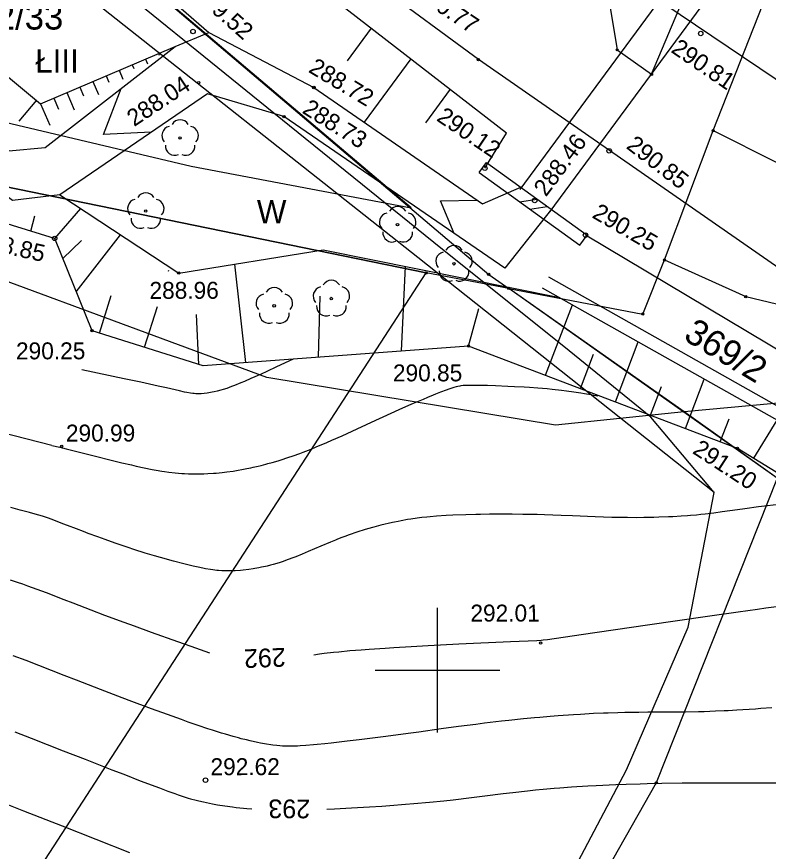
# Model space of a CAD drawing. Extents: x 7477803 to 7478145, y 5500698 to 5500984.
# Drawn here: x 7477883.12 to 7477913.26, y 5500892.73 to 5500926.22 of the extents above; entities that cross this region are included whole.
import ezdxf

# ---------------------------------------------------------------- set-up
doc = ezdxf.new("R2010")
doc.units = 0
for name, color, linetype in [('203-Punkt załamania granicy działki nie stabilizowany', 7, 'Continuous'), ('eNN', 7, 'Continuous'), ('eWN', 7, 'Continuous'), ('gr_dzialki', 7, 'Continuous'), ('gr_klasy', 7, 'Continuous'), ('gr_uzytek', 7, 'Continuous'), ('jezdnia', 7, 'Continuous'), ('murek', 7, 'Continuous'), ('nr_dzialki', 7, 'Continuous'), ('opis_klasy', 7, 'Continuous'), ('opis_uzytek', 7, 'Continuous'), ('pkt_wys', 7, 'Continuous'), ('przepust_rzut', 7, 'Continuous'), ('robocza49', 7, 'Continuous'), ('rowy', 7, 'Continuous'), ('skarp_wypel', 7, 'Continuous'), ('skarpa_gora', 7, 'Continuous'), ('warst_ciagla', 7, 'Continuous'), ('warst_opis', 7, 'Continuous'), ('warst_przeryw', 7, 'Continuous'), ('zielen', 7, 'Continuous')]:
    doc.layers.add(name, color=color, linetype=linetype)

# ---------------------------------------------------------------- blocks, each defined once
blk = doc.blocks.new('203')
blk.add_circle((0, 0), 0.045)
blk = doc.blocks.new('801_3')
at = {"layer": 'pkt_wys'}
blk.add_circle((0, 0), 0.045, dxfattribs=at)
blk.add_circle((0, 0), 0.045, dxfattribs=at)
blk = doc.blocks.new('922_5')
at = {"layer": 'zielen'}
blk.add_circle((-0.001, 0), 0.05, dxfattribs=at)
blk.add_circle((-0.001, 0), 0.05, dxfattribs=at)
for centre, start, end in [((0.004, 0.357), 30.1243, 149.8757), ((-0.353, 0.098), 101.9988, 221.9759), ((0.361, 0.098), 318.0241, 78.0012), ((-0.215, -0.321), 174.335, 293.7607), ((0.224, -0.321), 246.2393, 5.665)]:
    blk.add_arc(centre, 0.375, start, end, dxfattribs=at)
blk = doc.blocks.new('801_5')
at = {"layer": 'pkt_wys'}
blk.add_circle((0, 0), 0.05, dxfattribs=at)
blk.add_circle((0, 0), 0.05, dxfattribs=at)

msp = doc.modelspace()

# ---------------------------------------------------------------- linework, layer by layer
at = {"layer": 'eNN'}
msp.add_line((7477911.094, 5500907.132), (7477908.551, 5500910.148), dxfattribs=at)
msp.add_lwpolyline([(7477908.551, 5500910.148), (7477905.276, 5500912.813), (7477899.85, 5500917.156), (7477893.431, 5500922.355), (7477885.497, 5500928.781), (7477881.972, 5500929.954)], dxfattribs=at)
at = {"layer": 'eWN'}
msp.add_lwpolyline([(7477864.586, 5500830.869), (7477874.504, 5500845.51), (7477886.717, 5500863.094), (7477896.968, 5500876.013), (7477903.181, 5500887.651), (7477907.573, 5500896.009), (7477910.052, 5500901.721), (7477911.094, 5500907.132), (7477899.209, 5500916.554), (7477885.259, 5500927.591), (7477881.972, 5500929.954), (7477875.911, 5500934.547), (7477875.795, 5500934.654)], dxfattribs=at)
at = {"layer": 'gr_dzialki'}
for points in [[(7477905.2, 5500937.01), (7477907.2, 5500924.89)], [(7477877.66, 5500936.58), (7477902.05, 5500915.88)], [(7477908.58, 5500923.91), (7477911.91, 5500931.81)], [(7477911.05, 5500921.65), (7477914.31, 5500929.95)], [(7477907.2, 5500924.89), (7477908.58, 5500923.91)], [(7477909.1, 5500916.46), (7477911.05, 5500921.65)], [(7477911.05, 5500921.65), (7477913.61, 5500920.37)], [(7477880.41, 5500919.86), (7477899.54, 5500915.94)], [(7477908.23, 5500914.29), (7477909.1, 5500916.46)], [(7477909.1, 5500916.46), (7477912.36, 5500914.99)], [(7477867.65, 5500866.83), (7477899.54, 5500915.94)], [(7477902.85, 5500915.32), (7477899.54, 5500915.94)], [(7477902.05, 5500915.88), (7477902.85, 5500915.32)], [(7477913.62, 5500907.71), (7477902.85, 5500915.32)], [(7477902.85, 5500915.32), (7477908.23, 5500914.29)], [(7477912.36, 5500914.99), (7477916.11, 5500914.1)], [(7477913.62, 5500907.71), (7477908.77, 5500895.48)], [(7477908.77, 5500895.48), (7477894.92, 5500871.04)]]:
    msp.add_lwpolyline(points, dxfattribs=at)
at = {"layer": 'gr_klasy'}
for points in [[(7477898.94, 5500918.55), (7477879.178, 5500935.294)], [(7477881.9, 5500922.16), (7477890.12, 5500920.23)], [(7477890.12, 5500920.23), (7477898.94, 5500918.55)], [(7477893.15, 5500911.75), (7477871.161, 5500919.882)], [(7477899.54, 5500915.94), (7477880.41, 5500919.86)], [(7477902.85, 5500915.32), (7477899.54, 5500915.94)], [(7477909.89, 5500910.36), (7477902.85, 5500915.32)], [(7477904.73, 5500909.83), (7477893.15, 5500911.75)], [(7477909.89, 5500910.36), (7477904.73, 5500909.83)], [(7477913.62, 5500907.71), (7477909.89, 5500910.36)]]:
    msp.add_lwpolyline(points, dxfattribs=at)
at = {"layer": 'gr_uzytek'}
msp.add_lwpolyline([(7477929.78, 5500918.89), (7477938.86, 5500913.04), (7477909.89, 5500910.36)], dxfattribs=at)
at = {"layer": 'jezdnia'}
for points in [[(7477897.344, 5500935.024), (7477905.871, 5500928.923), (7477941.067, 5500905.192)], [(7477987.535, 5500870.412), (7477985.624, 5500871.53), (7477967.072, 5500882.45), (7477949.37, 5500893.011), (7477933.46, 5500902.673), (7477915.126, 5500915.133), (7477901.636, 5500924.498), (7477893.479, 5500930.51)]]:
    msp.add_lwpolyline(points, dxfattribs=at)
at = {"layer": 'murek'}
for p, q in [((7477901.667, 5500919.964), (7477901.96, 5500920.369)), ((7477901.96, 5500920.369), (7477905.993, 5500917.453)), ((7477901.667, 5500919.964), (7477905.7, 5500917.048)), ((7477903.288, 5500918.792), (7477903.986, 5500918.904)), ((7477903.693, 5500918.499), (7477904.391, 5500918.611)), ((7477905.7, 5500917.048), (7477905.993, 5500917.453))]:
    msp.add_line(p, q, dxfattribs=at)
at = {"layer": 'pkt_wys'}
for centre in [(7477890.19, 5500925.63), (7477910.553, 5500925.545), (7477906.881, 5500920.839), (7477901.895, 5500920.14), (7477903.895, 5500918.844), (7477905.932, 5500917.459), (7477884.641, 5500917.325), (7477890.69, 5500895.587)]:
    msp.add_circle(centre, 0.09, dxfattribs=at)
at = {"layer": 'przepust_rzut'}
for points in [[(7477910.779, 5500929.455), (7477903.291, 5500919.29)], [(7477911.987, 5500928.565), (7477904.499, 5500918.4)]]:
    msp.add_lwpolyline(points, dxfattribs=at)
at = {"layer": 'robocza49'}
for p, q in [((7477900, 5500897.5), (7477900, 5500902.5)), ((7477897.5, 5500900), (7477902.5, 5500900))]:
    msp.add_line(p, q, dxfattribs=at)
at = {"layer": 'rowy'}
for points in [[(7477872.777, 5500927.493), (7477873.773, 5500927.288), (7477878.954, 5500925.794), (7477882.8, 5500920.838), (7477884.259, 5500920.969), (7477889.475, 5500925.025), (7477890.824, 5500925.587), (7477895.037, 5500923.381), (7477901.802, 5500918.709), (7477903.365, 5500919.391)], [(7477904.573, 5500918.501), (7477902.695, 5500916.13), (7477893.838, 5500922.21), (7477890.767, 5500923.127), (7477884.852, 5500919.07), (7477882.952, 5500918.848), (7477877.738, 5500922.782), (7477873.234, 5500925.927), (7477872.495, 5500926.12)], [(7477888.516, 5500921.583), (7477886.602, 5500921.494), (7477887.31, 5500923.342)], [(7477900.658, 5500917.528), (7477900.117, 5500918.835), (7477901.575, 5500918.865)], [(7477993.882, 5500863.302), (7477915.697, 5500909.43), (7477904.458, 5500915.769)], [(7477993.629, 5500862.871), (7477915.447, 5500908.997), (7477904.213, 5500915.334)]]:
    msp.add_lwpolyline(points, dxfattribs=at)
at = {"layer": 'skarp_wypel'}
for p, q in [((7477897.341, 5500925.759), (7477896.374, 5500924.447)), ((7477889.329, 5500924.963), (7477889.339, 5500924.94)), ((7477888.804, 5500924.74), (7477888.83, 5500924.679)), ((7477887.753, 5500924.293), (7477887.82, 5500924.136)), ((7477888.279, 5500924.516), (7477888.36, 5500924.326)), ((7477898.922, 5500924.533), (7477897.048, 5500921.992)), ((7477887.228, 5500924.069), (7477887.381, 5500923.711)), ((7477886.178, 5500923.623), (7477886.402, 5500923.097)), ((7477886.703, 5500923.846), (7477886.81, 5500923.594)), ((7477885.653, 5500923.399), (7477885.801, 5500923.052)), ((7477900.503, 5500923.307), (7477899.51, 5500921.96)), ((7477883.906, 5500922.872), (7477883.2, 5500922.026)), ((7477884.603, 5500922.953), (7477884.791, 5500922.51)), ((7477885.128, 5500923.176), (7477885.423, 5500922.483)), ((7477884.078, 5500922.729), (7477884.443, 5500921.869)), ((7477884.641, 5500917.325), (7477885.686, 5500918.521)), ((7477883.691, 5500917.619), (7477883.841, 5500918.23)), ((7477884.969, 5500916.513), (7477885.721, 5500917.235)), ((7477885.505, 5500915.186), (7477887.28, 5500917.472)), ((7477892.308, 5500912.344), (7477891.862, 5500916.298)), ((7477898.556, 5500912.808), (7477898.711, 5500916.203)), ((7477889.208, 5500916.012), (7477889.219, 5500916.046)), ((7477886.437, 5500913.527), (7477886.912, 5500915.035)), ((7477895.223, 5500912.56), (7477895.289, 5500915.008)), ((7477888.246, 5500912.957), (7477888.759, 5500914.587)), ((7477901.238, 5500913.008), (7477901.656, 5500914.509)), ((7477904.329, 5500911.835), (7477905.406, 5500914.661)), ((7477890.422, 5500912.272), (7477890.325, 5500914.267)), ((7477907.133, 5500910.767), (7477908.048, 5500913.17)), ((7477905.731, 5500911.301), (7477906.258, 5500912.685)), ((7477909.936, 5500909.699), (7477910.691, 5500911.68)), ((7477908.534, 5500910.233), (7477908.974, 5500911.387)), ((7477911.338, 5500909.165), (7477911.69, 5500910.089)), ((7477912.677, 5500908.503), (7477913.613, 5500910.032))]:
    msp.add_line(p, q, dxfattribs=at)
at = {"layer": 'skarpa_gora'}
for points in [[(7477876.391, 5500937.758), (7477881.125, 5500933.996), (7477890.824, 5500925.587)], [(7477901.895, 5500920.141), (7477902.769, 5500921.55), (7477892.66, 5500929.389)], [(7477873.01, 5500928.626), (7477873.731, 5500928.508), (7477878.262, 5500927.583), (7477884.078, 5500922.729), (7477889.475, 5500925.025)], [(7477884.64, 5500917.325), (7477873.74, 5500920.698)], [(7477884.852, 5500919.07), (7477889.615, 5500915.935), (7477895.414, 5500916.872), (7477904.896, 5500914.948)], [(7477901.238, 5500913.008), (7477890.599, 5500912.216), (7477886.138, 5500913.622), (7477884.641, 5500917.325)], [(7477940.967, 5500896.534), (7477905.932, 5500917.459)], [(7478019.361, 5500843.679), (7478014.009, 5500848.521), (7477985, 5500865.71), (7477963.897, 5500877.826), (7477945.275, 5500888.626), (7477927.783, 5500899.247), (7477912.023, 5500908.9), (7477901.238, 5500913.008)]]:
    msp.add_lwpolyline(points, dxfattribs=at)
at = {"layer": 'warst_ciagla'}
for points in [[(7477884.531, 5500909.018), (7477875.396, 5500911.354), (7477875.396, 5500911.354), (7477866.858, 5500913.345)], [(7477884.531, 5500909.018), (7477884.845, 5500908.95), (7477884.902, 5500908.936), (7477884.924, 5500908.929), (7477884.94, 5500908.923), (7477884.957, 5500908.917), (7477885.097, 5500908.88), (7477885.85, 5500908.694), (7477887.337, 5500908.326), (7477887.717, 5500908.234), (7477887.916, 5500908.187), (7477888.226, 5500908.118), (7477888.547, 5500908.052), (7477888.712, 5500908.022), (7477888.934, 5500907.985), (7477889.046, 5500907.968), (7477889.217, 5500907.945), (7477889.475, 5500907.916), (7477889.736, 5500907.895), (7477889.853, 5500907.888), (7477890.01, 5500907.882), (7477890.089, 5500907.879), (7477890.267, 5500907.877), (7477890.386, 5500907.877), (7477890.547, 5500907.88), (7477890.627, 5500907.882), (7477890.789, 5500907.889), (7477891.006, 5500907.903), (7477891.115, 5500907.911), (7477891.363, 5500907.935), (7477891.55, 5500907.957), (7477891.801, 5500907.992), (7477891.928, 5500908.012), (7477892.215, 5500908.063), (7477892.343, 5500908.088), (7477892.515, 5500908.123), (7477892.602, 5500908.142), (7477892.797, 5500908.187), (7477892.928, 5500908.219), (7477893.104, 5500908.264), (7477893.192, 5500908.288), (7477893.369, 5500908.337), (7477893.606, 5500908.407), (7477893.726, 5500908.444), (7477893.996, 5500908.532), (7477894.2, 5500908.601), (7477894.474, 5500908.7), (7477894.612, 5500908.751), (7477894.925, 5500908.873), (7477895.134, 5500908.958), (7477895.552, 5500909.134), (7477895.76, 5500909.225), (7477896.173, 5500909.409), (7477896.578, 5500909.594), (7477897.35, 5500909.951), (7477898.136, 5500910.311), (7477898.455, 5500910.455), (7477898.852, 5500910.631), (7477899.038, 5500910.712), (7477899.428, 5500910.879), (7477899.607, 5500910.954), (7477899.83, 5500911.046), (7477899.934, 5500911.088), (7477900.129, 5500911.164), (7477900.361, 5500911.25), (7477900.465, 5500911.287), (7477900.668, 5500911.353), (7477900.754, 5500911.377), (7477900.807, 5500911.391), (7477900.902, 5500911.412), (7477900.946, 5500911.42), (7477901.028, 5500911.432), (7477901.107, 5500911.438), (7477901.158, 5500911.441), (7477901.266, 5500911.443), (7477901.475, 5500911.442), (7477901.813, 5500911.436), (7477902.006, 5500911.431), (7477902.328, 5500911.42), (7477902.816, 5500911.401), (7477903.085, 5500911.389), (7477903.471, 5500911.369), (7477903.68, 5500911.357), (7477904.017, 5500911.332), (7477904.389, 5500911.299), (7477904.59, 5500911.278), (7477904.97, 5500911.234), (7477905.166, 5500911.209), (7477905.46, 5500911.169), (7477905.748, 5500911.126), (7477905.886, 5500911.104), (7477906.146, 5500911.059), (7477906.265, 5500911.036), (7477906.428, 5500911.002)], [(7477890.869, 5500900.683), (7477890.113, 5500900.947), (7477889.576, 5500901.137), (7477888.527, 5500901.513), (7477887.838, 5500901.763), (7477887.424, 5500901.916), (7477886.657, 5500902.201), (7477886.102, 5500902.41), (7477885.377, 5500902.687), (7477885.02, 5500902.825), (7477884.31, 5500903.101), (7477883.944, 5500903.238), (7477883.56, 5500903.377), (7477883.36, 5500903.446), (7477883.153, 5500903.516), (7477882.866, 5500903.609)], [(7477913.81, 5500902.57), (7477913.164, 5500902.483), (7477912.83, 5500902.437), (7477912.051, 5500902.328), (7477910.824, 5500902.153), (7477908.423, 5500901.803), (7477905.759, 5500901.415), (7477904.406, 5500901.222), (7477904.233, 5500901.2), (7477904.155, 5500901.192), (7477903.978, 5500901.183), (7477902.922, 5500901.136), (7477900.852, 5500901.038), (7477899.617, 5500900.977), (7477898.945, 5500900.941), (7477898.247, 5500900.9), (7477897.891, 5500900.877), (7477897.253, 5500900.833), (7477896.938, 5500900.809), (7477896.476, 5500900.771), (7477896.038, 5500900.73), (7477895.83, 5500900.709), (7477895.444, 5500900.665), (7477895.268, 5500900.643), (7477895.03, 5500900.608)], [(7477883.044, 5500897.529), (7477883.703, 5500897.273), (7477884.979, 5500896.771), (7477885.863, 5500896.424), (7477886.927, 5500896.009), (7477887.411, 5500895.822), (7477888.075, 5500895.567), (7477888.847, 5500895.275), (7477889.184, 5500895.149), (7477889.458, 5500895.048), (7477889.591, 5500895.001), (7477889.788, 5500894.935), (7477889.989, 5500894.872), (7477890.093, 5500894.842), (7477890.312, 5500894.783), (7477890.428, 5500894.754), (7477890.614, 5500894.712), (7477890.851, 5500894.662), (7477890.977, 5500894.638), (7477891.17, 5500894.603), (7477891.469, 5500894.555), (7477891.771, 5500894.513), (7477891.921, 5500894.494), (7477892.212, 5500894.464), (7477892.352, 5500894.453), (7477892.551, 5500894.442)], [(7477895.551, 5500894.429), (7477895.866, 5500894.44), (7477896.086, 5500894.449), (7477896.548, 5500894.472), (7477897.272, 5500894.516), (7477897.762, 5500894.549), (7477898.085, 5500894.573), (7477898.71, 5500894.622), (7477899.043, 5500894.649), (7477899.669, 5500894.706), (7477900.255, 5500894.764), (7477900.629, 5500894.804), (7477901.356, 5500894.889), (7477901.898, 5500894.958), (7477902.635, 5500895.051), (7477903.016, 5500895.098), (7477903.61, 5500895.165), (7477903.92, 5500895.196), (7477904.239, 5500895.227), (7477904.68, 5500895.264), (7477904.908, 5500895.282), (7477905.375, 5500895.315), (7477906.027, 5500895.354), (7477906.364, 5500895.372), (7477907.152, 5500895.408), (7477907.561, 5500895.423), (7477908.121, 5500895.441), (7477908.408, 5500895.448), (7477908.995, 5500895.462), (7477909.805, 5500895.475), (7477910.222, 5500895.48), (7477911.189, 5500895.486), (7477911.687, 5500895.486), (7477912.699, 5500895.483), (7477913.712, 5500895.476)]]:
    msp.add_lwpolyline(points, dxfattribs=at)
at = {"layer": 'warst_przeryw'}
for points in [[(7477894.212, 5500912.485), (7477893.534, 5500912.166), (7477893.148, 5500911.987), (7477892.917, 5500911.882), (7477892.513, 5500911.701), (7477892.258, 5500911.59), (7477892.107, 5500911.526), (7477891.849, 5500911.421), (7477891.739, 5500911.378), (7477891.55, 5500911.309), (7477891.397, 5500911.259), (7477891.309, 5500911.233), (7477891.156, 5500911.193), (7477891.038, 5500911.165), (7477890.964, 5500911.15), (7477890.825, 5500911.124), (7477890.759, 5500911.114), (7477890.635, 5500911.099), (7477890.519, 5500911.091), (7477890.445, 5500911.088), (7477890.398, 5500911.088), (7477890.306, 5500911.091), (7477890.231, 5500911.096), (7477890.181, 5500911.101), (7477890.084, 5500911.114), (7477889.941, 5500911.14), (7477889.845, 5500911.16), (7477889.647, 5500911.206), (7477889.128, 5500911.326), (7477888.796, 5500911.401), (7477888.1, 5500911.553), (7477887.433, 5500911.695), (7477885.727, 5500912.057)], [(7477913.682, 5500906.65), (7477913.236, 5500906.596), (7477912.867, 5500906.549), (7477912.325, 5500906.476), (7477912.033, 5500906.435), (7477911.408, 5500906.348), (7477911.076, 5500906.304), (7477910.733, 5500906.263), (7477910.558, 5500906.244), (7477910.38, 5500906.227), (7477910.139, 5500906.206), (7477910.017, 5500906.196), (7477909.77, 5500906.178), (7477909.434, 5500906.158), (7477909.263, 5500906.15), (7477908.871, 5500906.135), (7477908.671, 5500906.129), (7477908.401, 5500906.124), (7477908.265, 5500906.122), (7477907.988, 5500906.12), (7477907.613, 5500906.122), (7477907.423, 5500906.124), (7477906.987, 5500906.133), (7477906.317, 5500906.156), (7477905.41, 5500906.194), (7477904.958, 5500906.212), (7477904.29, 5500906.234), (7477903.997, 5500906.241), (7477903.61, 5500906.249), (7477903.418, 5500906.252), (7477902.99, 5500906.256), (7477902.359, 5500906.257), (7477902.083, 5500906.255), (7477901.718, 5500906.25), (7477901.537, 5500906.246), (7477901.134, 5500906.236), (7477900.606, 5500906.218), (7477900.344, 5500906.205), (7477899.954, 5500906.179), (7477899.695, 5500906.157), (7477899.566, 5500906.144), (7477899.373, 5500906.123), (7477899.179, 5500906.098), (7477898.921, 5500906.061), (7477898.793, 5500906.04), (7477898.535, 5500905.995), (7477898.42, 5500905.973), (7477898.268, 5500905.942), (7477898.191, 5500905.926), (7477898.02, 5500905.888), (7477897.891, 5500905.858), (7477897.719, 5500905.816), (7477897.634, 5500905.794), (7477897.441, 5500905.742), (7477897.183, 5500905.668), (7477897.055, 5500905.629), (7477896.798, 5500905.547), (7477896.683, 5500905.509), (7477896.531, 5500905.457), (7477896.455, 5500905.43), (7477896.284, 5500905.368), (7477896.155, 5500905.319), (7477895.984, 5500905.253), (7477895.899, 5500905.219), (7477895.706, 5500905.14), (7477895.322, 5500904.976), (7477894.814, 5500904.757), (7477894.563, 5500904.651), (7477894.314, 5500904.55), (7477894.19, 5500904.503), (7477894.007, 5500904.435), (7477893.764, 5500904.352), (7477893.644, 5500904.314), (7477893.406, 5500904.244), (7477893.301, 5500904.215), (7477893.163, 5500904.18), (7477893.094, 5500904.163), (7477892.939, 5500904.129), (7477892.825, 5500904.105), (7477892.673, 5500904.077), (7477892.597, 5500904.064), (7477892.429, 5500904.039), (7477892.207, 5500904.013), (7477892.097, 5500904.003), (7477891.879, 5500903.989), (7477891.783, 5500903.986), (7477891.657, 5500903.984), (7477891.594, 5500903.984), (7477891.453, 5500903.987), (7477891.348, 5500903.991), (7477891.21, 5500904.001), (7477891.141, 5500904.007), (7477890.988, 5500904.024), (7477890.887, 5500904.038), (7477890.686, 5500904.071), (7477890.587, 5500904.089), (7477890.392, 5500904.13), (7477890.199, 5500904.174), (7477889.822, 5500904.268), (7477889.413, 5500904.377), (7477888.891, 5500904.521), (7477888.64, 5500904.593), (7477888.276, 5500904.701), (7477887.814, 5500904.846), (7477887.593, 5500904.918), (7477887.274, 5500905.026), (7477887.068, 5500905.098), (7477886.667, 5500905.242), (7477886.372, 5500905.349), (7477885.988, 5500905.491), (7477885.798, 5500905.562), (7477885.518, 5500905.668), (7477885.152, 5500905.808), (7477884.972, 5500905.877), (7477884.602, 5500906.019), (7477884.391, 5500906.094), (7477884.147, 5500906.174), (7477884.009, 5500906.217), (7477883.858, 5500906.262), (7477883.637, 5500906.325), (7477883.518, 5500906.358), (7477883.262, 5500906.427), (7477882.887, 5500906.525)], [(7477913.408, 5500898.494), (7477912.969, 5500898.457), (7477912.748, 5500898.44), (7477912.247, 5500898.405), (7477911.995, 5500898.39), (7477911.657, 5500898.372), (7477911.488, 5500898.364), (7477911.147, 5500898.35), (7477910.69, 5500898.335), (7477910.46, 5500898.329), (7477909.94, 5500898.319), (7477909.15, 5500898.314), (7477908.433, 5500898.312), (7477908.069, 5500898.309), (7477907.511, 5500898.301), (7477907.228, 5500898.294), (7477906.844, 5500898.281), (7477906.65, 5500898.274), (7477906.258, 5500898.256), (7477905.725, 5500898.227), (7477905.454, 5500898.21), (7477904.835, 5500898.166), (7477904.52, 5500898.141), (7477904.095, 5500898.104), (7477903.881, 5500898.085), (7477903.446, 5500898.043), (7477902.858, 5500897.982), (7477902.56, 5500897.949), (7477901.879, 5500897.869), (7477901.533, 5500897.826), (7477900.837, 5500897.736), (7477900.146, 5500897.643), (7477899.25, 5500897.52), (7477898.821, 5500897.461), (7477897.917, 5500897.34), (7477896.85, 5500897.204), (7477896.374, 5500897.146), (7477895.735, 5500897.073), (7477895.478, 5500897.046), (7477895.164, 5500897.015), (7477895.018, 5500897.001), (7477894.718, 5500896.976), (7477894.483, 5500896.96), (7477894.375, 5500896.954), (7477894.22, 5500896.948), (7477894.071, 5500896.946), (7477893.998, 5500896.947), (7477893.853, 5500896.951), (7477893.779, 5500896.955), (7477893.667, 5500896.964), (7477893.551, 5500896.975), (7477893.39, 5500896.994), (7477893.307, 5500897.005), (7477893.136, 5500897.032), (7477892.896, 5500897.075), (7477892.772, 5500897.1), (7477892.48, 5500897.164), (7477892.329, 5500897.2), (7477892.12, 5500897.252), (7477892.013, 5500897.281), (7477891.794, 5500897.341), (7477891.492, 5500897.428), (7477891.335, 5500897.475), (7477890.973, 5500897.59), (7477890.785, 5500897.651), (7477890.4, 5500897.781), (7477890.001, 5500897.92), (7477889.728, 5500898.017), (7477889.17, 5500898.219), (7477888.524, 5500898.456), (7477887.635, 5500898.788), (7477887.177, 5500898.96), (7477886.477, 5500899.227), (7477885.514, 5500899.598), (7477885.02, 5500899.791), (7477884.01, 5500900.185), (7477883.495, 5500900.384), (7477882.974, 5500900.579)], [(7477882.593, 5500894.675), (7477883.395, 5500894.36), (7477884.938, 5500893.751), (7477887.644, 5500892.684)]]:
    msp.add_lwpolyline(points, dxfattribs=at)

# ---------------------------------------------------------------- block references
at = {"layer": '203-Punkt załamania granicy działki nie stabilizowany'}
for p in [(7477907.2, 5500924.89), (7477908.58, 5500923.91), (7477911.05, 5500921.65), (7477909.1, 5500916.46), (7477899.54, 5500915.94), (7477902.05, 5500915.88), (7477902.85, 5500915.32), (7477912.36, 5500914.99), (7477908.23, 5500914.29), (7477908.77, 5500895.48)]:
    msp.add_blockref('203', p, dxfattribs=at)
at = {"layer": 'pkt_wys', "rotation": 0.0626175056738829}
for name, p in [('801_3', (7477901.636, 5500924.498)), ('801_5', (7477890.417, 5500923.576)), ('801_5', (7477895.037, 5500923.381)), ('801_5', (7477893.838, 5500922.21)), ('801_3', (7477889.615, 5500915.935)), ('801_3', (7477886.138, 5500913.622)), ('801_3', (7477901.238, 5500913.008)), ('801_3', (7477884.923, 5500908.99)), ('801_3', (7477912.023, 5500908.9)), ('801_3', (7477904.131, 5500901.091))]:
    msp.add_blockref(name, p, dxfattribs=at)
at = {"layer": 'zielen', "rotation": 0.0626175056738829}
for p in [(7477889.669, 5500921.355), (7477888.292, 5500918.424), (7477898.393, 5500917.875), (7477900.655, 5500916.307), (7477895.736, 5500914.912), (7477893.446, 5500914.62)]:
    msp.add_blockref('922_5', p, dxfattribs=at)

# ---------------------------------------------------------------- texts
at = {"layer": 'nr_dzialki'}
msp.add_text('362/33', height=1.04, dxfattribs=at).set_placement((7477880.733, 5500925.705))
msp.add_text('369/2', height=1.04, rotation=328.8249, dxfattribs=at).set_placement((7477909.815, 5500913.287))
at = {"layer": 'opis_klasy'}
msp.add_text('ŁIII', height=0.94, dxfattribs=at).set_placement((7477883.86, 5500923.977))
at = {"layer": 'opis_uzytek'}
msp.add_text('W', height=0.94, dxfattribs=at).set_placement((7477892.75, 5500917.93))
at = {"layer": 'pkt_wys'}
for s, rotation, p in [('289.52', 318.2925, (7477890.142, 5500927.102)), ('290.77', 326.1115, (7477899.039, 5500927.065)), ('290.81', 325.5637, (7477909.324, 5500924.821)), ('288.72', 329.0593, (7477894.784, 5500924.02)), ('288.04', 33.6133, (7477887.828, 5500921.79)), ('288.73', 327.787, (7477894.531, 5500922.382)), ('290.12', 325.7959, (7477899.92, 5500922.076)), ('288.46', 53.1097, (7477904.344, 5500918.967)), ('290.85', 322.2454, (7477907.528, 5500920.968)), ('290.25', 329.8012, (7477906.158, 5500918.18)), ('288.85', 347.7377, (7477881.455, 5500916.969)), ('288.96', 0.0626, (7477888.444, 5500914.9)), ('290.25', 0.0626, (7477883.09, 5500912.472)), ('290.85', 0.0626, (7477898.208, 5500911.588)), ('290.99', 0.0626, (7477885.092, 5500909.174)), ('291.20', 326.8098, (7477910.185, 5500908.727)), ('292.01', 0.0626, (7477901.315, 5500901.951)), ('292.62', 0.0626, (7477890.89, 5500895.787))]:
    msp.add_text(s, height=0.68, rotation=rotation, dxfattribs=at).set_placement(p)
at = {"layer": 'warst_opis'}
for s, rotation, p in [('292', 182.2386, (7477893.893, 5500900.898)), ('293', 179.7585, (7477894.889, 5500894.807))]:
    msp.add_text(s, height=0.75, rotation=rotation, dxfattribs=at).set_placement(p)

doc.saveas('drawing.dxf')
